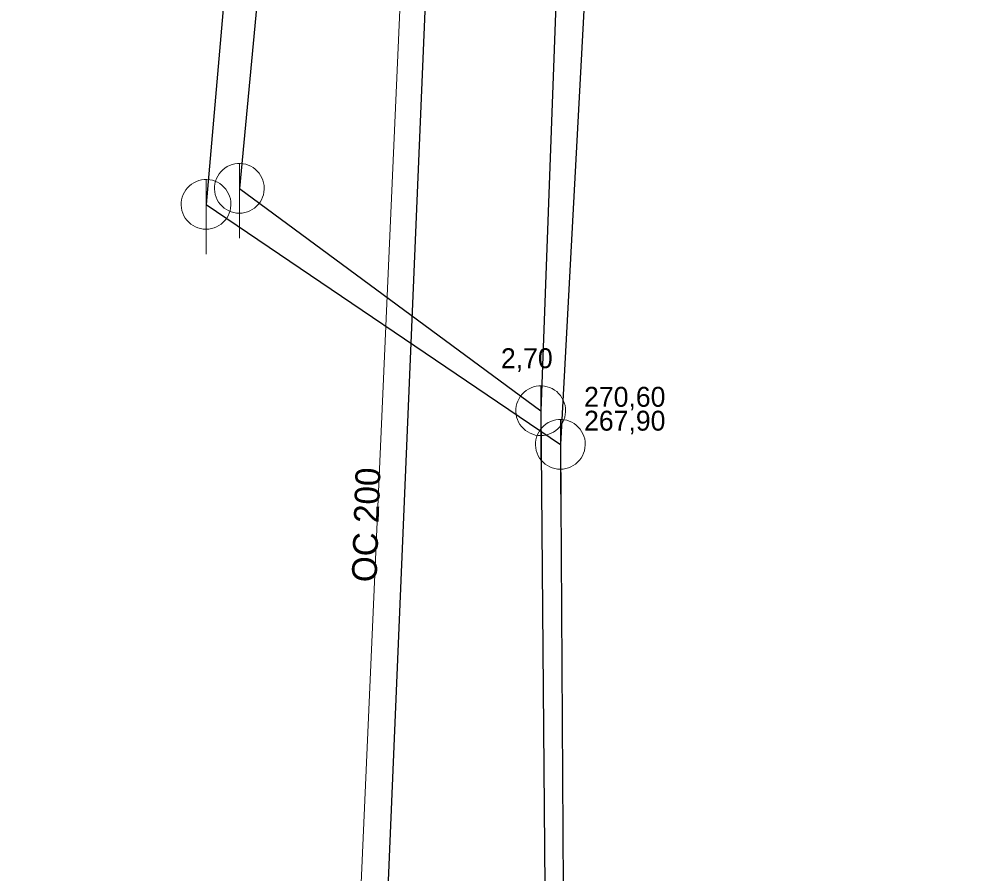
# Model space of a CAD drawing. Extents: x -725153 to -724843, y -978146 to -977794.
# Drawn here: x -724949.34 to -724911.38, y -978017.43 to -977983.08 of the extents above; entities that cross this region are included whole.
import ezdxf

# ---------------------------------------------------------------- set-up
doc = ezdxf.new("R2010")
doc.units = 0
doc.header["$LTSCALE"] = 0.32
doc.layers.add('1', color=7, linetype='Continuous')
for name, color, linetype, lineweight in [('13', 7, 'Continuous', 13), ('14', 7, 'Continuous', 25), ('17', 7, 'Continuous', 25), ('22', 7, 'Continuous', 13)]:
    doc.layers.add(name, color=color, linetype=linetype, lineweight=lineweight)

msp = doc.modelspace()

# ---------------------------------------------------------------- linework, layer by layer
at = {"layer": '13'}
msp.add_lwpolyline([(-724933.498, -977970.916), (-724936.609, -978041.12), (-724949.342, -978040.159)], dxfattribs=at)
at = {"layer": '14'}
for p, q in [((-724938.046, -977964.432), (-724940.477, -977989.897)), ((-724939.603, -977965.365), (-724941.816, -977990.541)), ((-724940.477, -977989.897), (-724928.359, -977998.839)), ((-724941.816, -977990.541), (-724927.569, -978000.189))]:
    msp.add_line(p, q, dxfattribs=at)
for points in [[(-724924.849, -977949.559), (-724927.569, -978000.189), (-724927.274, -978049.14)], [(-724926.682, -977953.405), (-724928.359, -977998.839), (-724927.944, -978048.326)]]:
    msp.add_lwpolyline(points, dxfattribs=at)
at = {"layer": '17'}
msp.add_lwpolyline([(-724911.375, -978083.783), (-724931.616, -978079.579), (-724929.686, -978057.78), (-724935.405, -978039.66), (-724932.296, -977965.921)], dxfattribs=at)
at = {"layer": '22'}
for p, q in [((-724940.477, -977991.897), (-724940.476, -977988.897)), ((-724941.816, -977992.541), (-724941.815, -977989.541)), ((-724928.359, -978000.839), (-724928.358, -977997.839)), ((-724927.569, -978002.189), (-724927.568, -977999.189))]:
    msp.add_line(p, q, dxfattribs=at)
for points in [[(-724939.477, -977989.897), (-724939.482, -977989.788), (-724939.5, -977989.68), (-724939.53, -977989.574), (-724939.57, -977989.473), (-724939.622, -977989.376), (-724939.684, -977989.286), (-724939.756, -977989.203), (-724939.836, -977989.129), (-724939.924, -977989.063), (-724940.018, -977989.008), (-724940.118, -977988.963), (-724940.223, -977988.93), (-724940.33, -977988.908), (-724940.439, -977988.898), (-724940.549, -977988.9), (-724940.657, -977988.914), (-724940.764, -977988.939), (-724940.867, -977988.976), (-724940.965, -977989.025), (-724941.057, -977989.083), (-724941.143, -977989.152), (-724941.22, -977989.229), (-724941.289, -977989.315), (-724941.348, -977989.407), (-724941.396, -977989.505), (-724941.433, -977989.608), (-724941.459, -977989.715), (-724941.473, -977989.823), (-724941.476, -977989.933), (-724941.466, -977990.042), (-724941.445, -977990.149), (-724941.411, -977990.253), (-724941.367, -977990.353), (-724941.312, -977990.448), (-724941.246, -977990.536), (-724941.172, -977990.616), (-724941.089, -977990.688), (-724940.999, -977990.75), (-724940.903, -977990.802), (-724940.801, -977990.843), (-724940.696, -977990.873), (-724940.588, -977990.891), (-724940.478, -977990.897), (-724940.369, -977990.891), (-724940.261, -977990.873), (-724940.156, -977990.844), (-724940.054, -977990.803), (-724939.957, -977990.751), (-724939.867, -977990.689), (-724939.784, -977990.618), (-724939.709, -977990.538), (-724939.644, -977990.45), (-724939.588, -977990.356), (-724939.544, -977990.256), (-724939.51, -977990.152), (-724939.488, -977990.044), (-724939.478, -977989.935)], [(-724940.816, -977990.541), (-724940.821, -977990.432), (-724940.839, -977990.324), (-724940.869, -977990.218), (-724940.909, -977990.117), (-724940.961, -977990.02), (-724941.023, -977989.93), (-724941.095, -977989.847), (-724941.175, -977989.773), (-724941.263, -977989.707), (-724941.357, -977989.652), (-724941.457, -977989.607), (-724941.562, -977989.574), (-724941.669, -977989.552), (-724941.778, -977989.542), (-724941.888, -977989.544), (-724941.996, -977989.558), (-724942.103, -977989.583), (-724942.206, -977989.62), (-724942.304, -977989.669), (-724942.396, -977989.727), (-724942.482, -977989.796), (-724942.559, -977989.873), (-724942.628, -977989.959), (-724942.687, -977990.051), (-724942.735, -977990.149), (-724942.772, -977990.252), (-724942.798, -977990.359), (-724942.812, -977990.467), (-724942.815, -977990.577), (-724942.805, -977990.686), (-724942.784, -977990.793), (-724942.75, -977990.897), (-724942.706, -977990.997), (-724942.651, -977991.092), (-724942.585, -977991.18), (-724942.511, -977991.26), (-724942.428, -977991.332), (-724942.338, -977991.394), (-724942.242, -977991.446), (-724942.14, -977991.487), (-724942.035, -977991.517), (-724941.927, -977991.535), (-724941.817, -977991.541), (-724941.708, -977991.535), (-724941.6, -977991.517), (-724941.495, -977991.488), (-724941.393, -977991.447), (-724941.296, -977991.395), (-724941.206, -977991.333), (-724941.123, -977991.262), (-724941.048, -977991.182), (-724940.983, -977991.094), (-724940.927, -977991), (-724940.883, -977990.9), (-724940.849, -977990.796), (-724940.827, -977990.688), (-724940.817, -977990.579)], [(-724927.359, -977998.839), (-724927.364, -977998.73), (-724927.382, -977998.622), (-724927.412, -977998.516), (-724927.452, -977998.415), (-724927.504, -977998.318), (-724927.566, -977998.228), (-724927.638, -977998.145), (-724927.718, -977998.071), (-724927.806, -977998.005), (-724927.9, -977997.95), (-724928, -977997.905), (-724928.105, -977997.872), (-724928.212, -977997.85), (-724928.321, -977997.84), (-724928.431, -977997.842), (-724928.539, -977997.856), (-724928.646, -977997.881), (-724928.749, -977997.918), (-724928.847, -977997.967), (-724928.939, -977998.025), (-724929.025, -977998.094), (-724929.102, -977998.171), (-724929.171, -977998.257), (-724929.23, -977998.349), (-724929.278, -977998.447), (-724929.315, -977998.55), (-724929.341, -977998.657), (-724929.355, -977998.765), (-724929.358, -977998.875), (-724929.348, -977998.984), (-724929.327, -977999.091), (-724929.293, -977999.195), (-724929.249, -977999.295), (-724929.194, -977999.39), (-724929.128, -977999.478), (-724929.054, -977999.558), (-724928.971, -977999.63), (-724928.881, -977999.692), (-724928.785, -977999.744), (-724928.683, -977999.785), (-724928.578, -977999.815), (-724928.47, -977999.833), (-724928.36, -977999.839), (-724928.251, -977999.833), (-724928.143, -977999.815), (-724928.038, -977999.786), (-724927.936, -977999.745), (-724927.839, -977999.693), (-724927.749, -977999.631), (-724927.666, -977999.56), (-724927.591, -977999.48), (-724927.526, -977999.392), (-724927.47, -977999.298), (-724927.426, -977999.198), (-724927.392, -977999.094), (-724927.37, -977998.986), (-724927.36, -977998.877)], [(-724926.569, -978000.189), (-724926.574, -978000.08), (-724926.592, -977999.972), (-724926.622, -977999.866), (-724926.662, -977999.765), (-724926.714, -977999.668), (-724926.776, -977999.578), (-724926.848, -977999.495), (-724926.928, -977999.421), (-724927.016, -977999.355), (-724927.11, -977999.3), (-724927.21, -977999.255), (-724927.315, -977999.222), (-724927.422, -977999.2), (-724927.531, -977999.19), (-724927.641, -977999.192), (-724927.749, -977999.206), (-724927.856, -977999.231), (-724927.959, -977999.268), (-724928.057, -977999.317), (-724928.149, -977999.375), (-724928.235, -977999.444), (-724928.312, -977999.521), (-724928.381, -977999.607), (-724928.44, -977999.699), (-724928.488, -977999.797), (-724928.525, -977999.9), (-724928.551, -978000.007), (-724928.565, -978000.115), (-724928.568, -978000.225), (-724928.558, -978000.334), (-724928.537, -978000.441), (-724928.503, -978000.545), (-724928.459, -978000.645), (-724928.404, -978000.74), (-724928.338, -978000.828), (-724928.264, -978000.908), (-724928.181, -978000.98), (-724928.091, -978001.042), (-724927.995, -978001.094), (-724927.893, -978001.135), (-724927.788, -978001.165), (-724927.68, -978001.183), (-724927.57, -978001.189), (-724927.461, -978001.183), (-724927.353, -978001.165), (-724927.248, -978001.136), (-724927.146, -978001.095), (-724927.049, -978001.043), (-724926.959, -978000.981), (-724926.876, -978000.91), (-724926.801, -978000.83), (-724926.736, -978000.742), (-724926.68, -978000.648), (-724926.636, -978000.548), (-724926.602, -978000.444), (-724926.58, -978000.336), (-724926.57, -978000.227)]]:
    msp.add_lwpolyline(points, close=True, dxfattribs=at)

# ---------------------------------------------------------------- texts
at = {"layer": '1'}
msp.add_text('2,70', height=0.8, dxfattribs=at).set_placement((-724929.959, -977997.127))
msp.add_text('OC 200', height=1, rotation=88, dxfattribs=at).set_placement((-724934.961, -978005.746))
at = {"layer": '22'}
for s, p in [('270,60', (-724926.616, -977998.678)), ('267,90', (-724926.616, -977999.638))]:
    msp.add_text(s, height=0.8, dxfattribs=at).set_placement(p)

doc.saveas('drawing.dxf')
